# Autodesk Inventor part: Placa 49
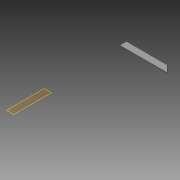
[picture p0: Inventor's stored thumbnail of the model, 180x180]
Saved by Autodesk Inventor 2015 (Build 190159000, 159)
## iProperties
Created: 2015-04
Part Number: Placa 49
Material: Generic
Document SubType Name: Modeling
Designer: suporte
Density: 1 g/cm^3
Appearance: Default
Author: suporte
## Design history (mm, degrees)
workplane "Work Plane1"
sketch "Sketch1"
  geometry: L1 (-650, 1450)-(-50.237, 1450) reference; L2 (-650, 1537.5)-(-650, -262.5) reference; L3 (568.362, 1437.5)-(668.362, 1437.5) reference; L4 (668.362, 1437.5)-(950, 1156.058) reference; L5 (568.362, 1537.5)-(49.763, 1537.5) reference; L6 (668.362, 1437.5)-(568.293, 1537.5); L7 (568.293, 1537.5)-(40.698, 1537.5); L8 (-50.237, 1437.5)-(-50.237, 1537.5); L9 (-50.237, 1537.5)-(40.698, 1537.5); L10 (-50.237, 1437.5)-(668.362, 1437.5); 2 further points
  constraints: 10 end point, 2 collinear, 2 point on line, 1 horizontal, 1 midpoint, 1 perpendicular, 1 vertical, 1 other
extrude "Extrusion1" new body sketch "Sketch1" distance "d0" = 12.5; taper "d1" = 0 deg
body "Solid1"
node "Reference1"
node "Reference2"
node "Reference3"
node "Reference4"
node "Reference5"
